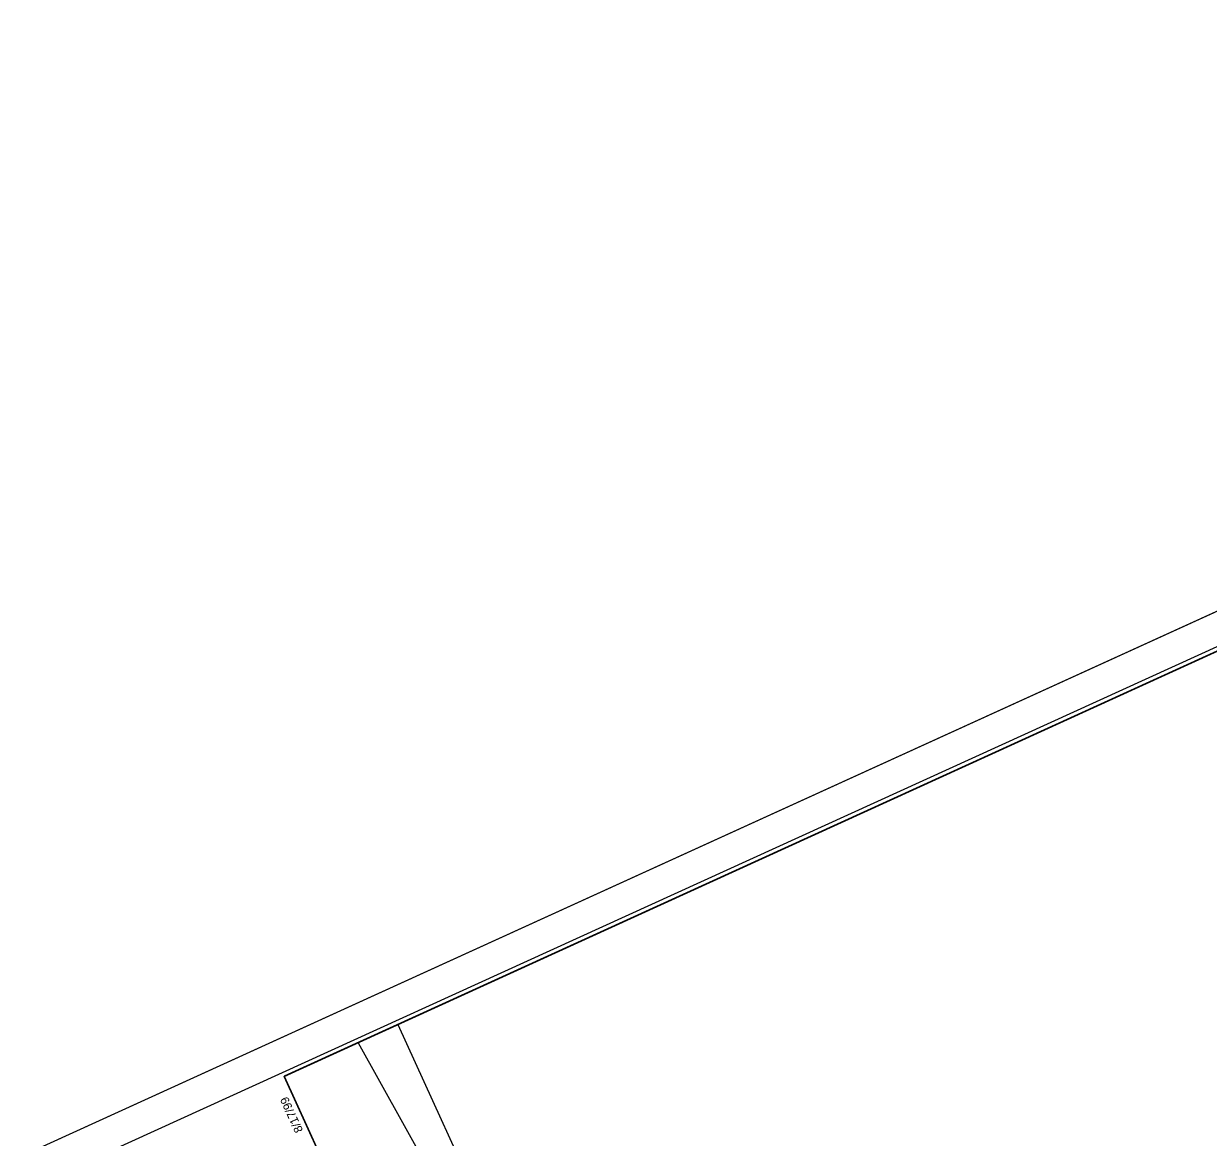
# Model space of a CAD drawing. Extents: x 2247864 to 2249896, y 662531 to 664296.
# Drawn here: x 2247910 to 2248641, y 663539 to 664226 of the extents above; entities that cross this region are included whole.
import ezdxf

# ---------------------------------------------------------------- set-up
doc = ezdxf.new("R2010")
doc.units = 0
for name, color, linetype in [('Sheet Clip Boundary CELL', 7, 'Continuous'), ('Sheet Cutting Line CELL', 7, 'Continuous'), ('Sheet Layout Plan Border', 7, 'Continuous'), ('Sheet Plan CELL', 7, 'Continuous'), ('Sheet Plan Layout CELL', 7, 'Continuous'), ('Sheet Plot Border Inside CELL', 7, 'Continuous'), ('Sheet Plot Border Outside CELL', 7, 'Continuous')]:
    doc.layers.add(name, color=color, linetype=linetype)

msp = doc.modelspace()

# ---------------------------------------------------------------- linework, layer by layer
at = {"layer": 'Sheet Clip Boundary CELL'}
msp.add_lwpolyline([(2248241.67, 663371.06), (2248514.44, 662770.57), (2248551.22, 662641.58), (2249564.56, 663103.35), (2249531.17, 663176.64), (2249788.88, 663294.08), (2249780.68, 663312.06), (2249743.43, 663294.89), (2249677.44, 663353.62), (2249425.27, 663908.72), (2249477.5, 663985.14), (2249305.27, 663906.66), (2249217.58, 664099.11), (2248115.83, 663597.06)], close=True, dxfattribs=at)
at = {"layer": 'Sheet Cutting Line CELL'}
msp.add_line((2249441.45, 664225.83), (2247909.5, 663527.75), dxfattribs=at)
at = {"layer": 'Sheet Layout Plan Border'}
msp.add_lwpolyline([(2248198.13, 663481.51), (2248575.77, 662652.77), (2249849.75, 663233.3), (2249502.05, 663996.33), (2249329.83, 663917.85), (2249242.13, 664110.3), (2248140.38, 663608.25)], close=True, dxfattribs=at)
at = {"layer": 'Sheet Plan CELL'}
msp.add_line((2248070.33, 663576.33), (2248070.33, 663576.33), dxfattribs=at)
for points in [[(2249435.32, 664198.33), (2248070.33, 663576.33), (2248505.72, 662620.85), (2249870.7, 663242.85)], [(2248505.72, 662620.85), (2248070.31, 663576.29), (2249253.26, 664115.38), (2249315.49, 663978.83), (2249497.53, 664061.77), (2249870.7, 663242.85)]]:
    msp.add_lwpolyline(points, close=True, dxfattribs=at)
at = {"layer": 'Sheet Plan Layout CELL'}
msp.add_lwpolyline([(2248070.31, 663576.29), (2248505.72, 662620.85), (2249870.68, 663242.84), (2249522.99, 664005.87), (2249305.27, 663906.66), (2249217.58, 664099.11)], close=True, dxfattribs=at)
at = {"layer": 'Sheet Plot Border Inside CELL'}
msp.add_lwpolyline([(2248367.09, 662554.92), (2249883.1, 663245.75), (2249445.65, 664205.77), (2247929.62, 663514.94)], close=True, dxfattribs=at)
at = {"layer": 'Sheet Plot Border Outside CELL'}
msp.add_lwpolyline([(2248363.56, 662531.33), (2249895.5, 663229.41), (2249441.45, 664225.83), (2247909.5, 663527.75)], close=True, dxfattribs=at)

# ---------------------------------------------------------------- texts
at = {"layer": 'Sheet Plan CELL'}
msp.add_text('8/17/99', height=5.25, rotation=114.49795, dxfattribs=at).set_placement((2248082, 663542.94))

doc.saveas('drawing.dxf')
